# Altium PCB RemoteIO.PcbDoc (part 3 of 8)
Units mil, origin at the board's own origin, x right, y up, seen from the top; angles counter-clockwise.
Board outline 7874.02 x 2362.2 mil, 6 copper layers (Top Layer, GND1, Layer 2, PWR, GND2, Bottom Layer), stack 60.956 mil thick; 655 components, 447 nets, 2607 pads, 1444 vias.
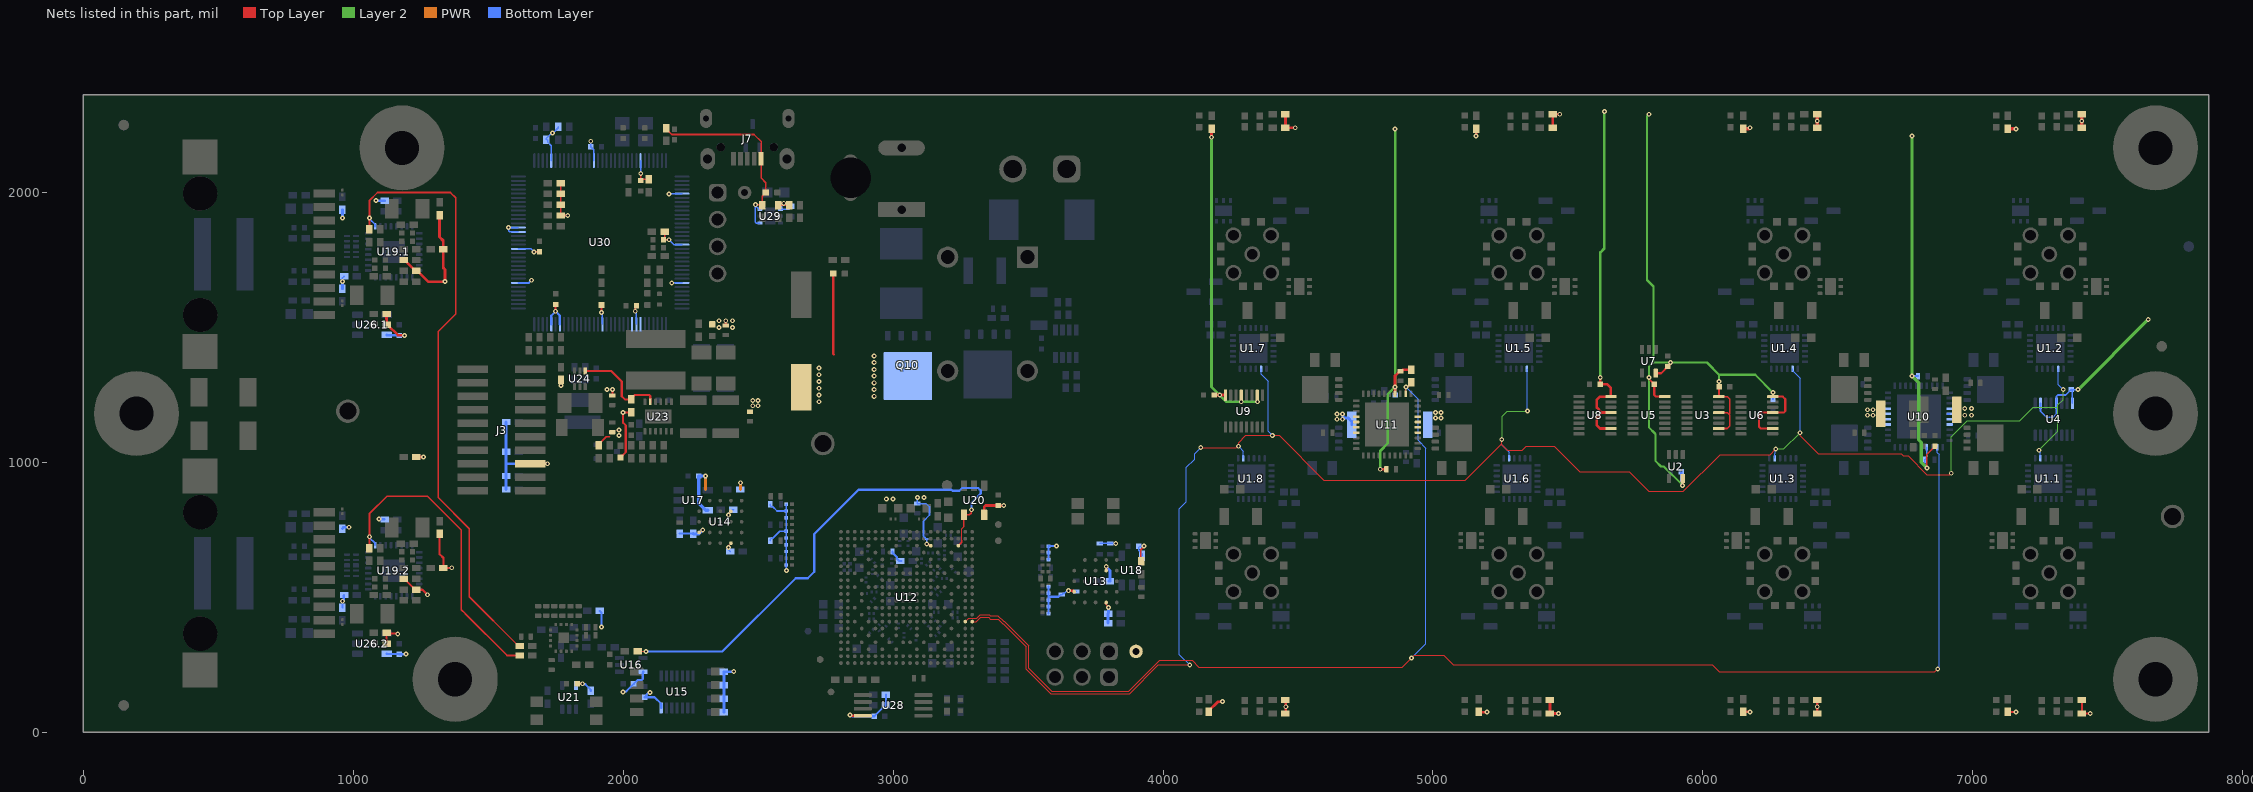
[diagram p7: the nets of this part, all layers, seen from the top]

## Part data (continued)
C11 C12 C13 C14 C16 C17 C18 C19: library part CMP-0119538-1, "WCAP-CSGP Multilayer Ceramic Chip Capacitor, General Purpose, size 0805, X7R, 22nF, 100VDC", Capacitance Tolerance=+/-10%, Case/Size Code=0805, Insulation Resistance=4.5GOhm, Manufacturer="Wurth Elektronik", Operating Temperature Max=125°C, Operating Temperature Min=-55°C, Rated Voltage (DC)=100V
C15 C20: library part CMP-0097308-1, "100 pF ±5% 100V Ceramic Capacitor C0G, NP0 0402 (1005 Metric)", Digikey Part Number=732-12055-1-ND, Manufacturer="Wurth Electronics", Mouser Part Number=710-885012005080, Operating Temperature Range="-55°C to +125°C", TempCo=30ppm/°C, Temperature Characteristic=NP0, Tolerance_%=5%, ValueDisplayed=100pF
C21 C22 C148 C163: library part CMP-0119705-1, "WCAP-CSGP Multilayer Ceramic Chip Capacitor, General Purpose, size 1210, X7R, 2.2µF, 100VDC", Capacitance Tolerance=+/-10%, Case/Size Code=1210, Insulation Resistance=0.05GOhm, Manufacturer="Wurth Elektronik", Operating Temperature Max=125°C, Operating Temperature Min=-55°C, PartNumber='885012209071, Rated Voltage (DC)=100V
C25 C26 C27 C28 C29 C32 C35 C39 C41 C42 C43 C130.1 C130.2 C133.1 C133.2 C136.1 C136.2 C138.1 C138.2 C144 C146 C154 C155 C158 C159 C164: library part CMP-0064924-2, "CAP, CERM, 1 uF, 10 V,+/- 20%, X5R, 0402", Cap_Case=0402, Manufacturer="Wurth Elektronik", Supplier Part Number 1=732-7489-1-ND, TempCo=X5R, Tolerance_%=20%, Value1=Unknown, Value2=10V, ValueDisplayed=1uF
C31 C131.1 C131.2 C134.1 C134.2 C145 C147 C156: library part CMP-0119242-1, "WCAP-CSGP Multilayer Ceramic Chip Capacitor, General Purpose, size 0402, X7R, 10nF, 10VDC", Capacitance Tolerance=+/-10%, Case/Size Code=0402, Insulation Resistance=10GOhm, Manufacturer="Wurth Elektronik", Operating Temperature Max=125°C, Operating Temperature Min=-55°C, Rated Voltage (DC)=10V
C44 C45 C46 C61 C63 C65 C66 C75 C84 C86 C91 C92 C93 C100 C121 C123 C125: library part CMP-0119149-1, "WCAP-CSGP Multilayer Ceramic Chip Capacitor, General Purpose, size 0603, X5R, 4.7µF, 6.3VDC", Capacitance Tolerance=+/-20%, Case/Size Code=0603, Insulation Resistance=0.02GOhm, Manufacturer="Wurth Elektronik", Operating Temperature Max=85°C, Operating Temperature Min=-55°C, Rated Voltage (DC)=6.3V
C47 C48 C49 C50 C51 C52 C53 C54 C55 C56 C57 C58 C59 C60 C62 C64 C67 C68 C69 C70 C71 C72 C73 C74 C76 C77 C78 C79 C80 C81 C82 C83 C85 C87 C88 C89 C90 C94 C95 C96 C97 C98 C99 C101 C102 C122 C124 C126: library part CMP-0119120-1, "WCAP-CSGP Multilayer Ceramic Chip Capacitor, General Purpose, size 0201, X5R Class II, 100nF, 6.3VDC", Capacitance Tolerance=+/-10%, Case/Size Code=0201, Insulation Resistance=0.5GOhm, Manufacturer="Wurth Elektronik", Operating Temperature Max=85°C, Operating Temperature Min=-55°C, Rated Voltage (DC)=6.3V
C104 C105 C106 C107 C120: library part CMP-0096739-1, "4.7 µF ±10% 50V Ceramic Capacitor X7R 1210 (3225 Metric)", Digikey Part Number=732-7386-1-ND, Manufacturer=Wurth, Mouser Part Number=710-885012209048, Operating Temperature Range="-55°C to +125°C", TempCo=15%, Temperature Characteristic=X7R, Tolerance_%=10%, ValueDisplayed=4.7uF
C108 C109 C115: library part CMP-0064937-2, "CAP, CERM, 22 uF, 10 V,+/- 10%, X7R, 1206", Cap_Case=1206, Manufacturer="Wurth Elektronik", Supplier Part Number 1=732-7566-1-ND, TempCo=X7R, Tolerance_%=10%, Value1=Unknown, Value2=10V, ValueDisplayed=22uF
C110 C111 C113 C129.1 C129.2 C132.1 C132.2: library part CMP-0750070-1, "CAP, CERM, 10 µF, 16 V,+/- 10%, X7R, 1206", Cap_Case=1206, Manufacturer="Wurth Elektronik", TempCo=X7R, Tolerance_%=10%, Value2=16V, ValueDisplayed=10µF
C112 C114: library part CMP-0112443-1, "WCAP-CSRF Multilayer Ceramic Chip Capacitor, High Frequency, size 0402, NP0 Class I, 27pF, 50VDC", Capacitance Tolerance=+/-5%, Case/Size Code=0402, Insulation Resistance=10GOhm, Manufacturer="Wurth Elektronik", Operating Temperature Max=125°C, Operating Temperature Min=-55°C, Rated Voltage (DC)=50V
C116: library part CMP-0114361-1, "WCAP-AS5H Aluminum Electrolytic Capacitor, V-Chip, D10 x H10.5mm, 220µF, 35V", Capacitance Tolerance=+/-20%, Leakage Current=77uA, Manufacturer="Wurth Elektronik", Operating Temperature Max=105°C, Operating Temperature Min=-40°C, Rated Voltage (DC)=35V, Ripple Current=280mA
C118: library part CMP-0119630-1, "WCAP-CSGP Multilayer Ceramic Chip Capacitor, General Purpose, size 1206, X7R, 100nF, 50VDC", Capacitance Tolerance=+/-10%, Case/Size Code=1206, Insulation Resistance=5GOhm, Manufacturer="Wurth Elektronik", Operating Temperature Max=125°C, Operating Temperature Min=-55°C, Rated Voltage (DC)=50V
C119: library part CMP-0077091-1, "CAP, CERM, 27 pF, 25 V,+/- 5%, C0G/NP0, 0402", Cap_Case=0402, Manufacturer=MuRata, Supplier Part Number 1=490-6176-1-ND, TempCo=C0G/NP0, Tolerance_%=5%, Value2=25V, ValueDisplayed=27pF
C127.1 C127.2: library part CMP-0006473-2, "CAP, CERM, 4.7 pF, 50 V, +/- 1%, C0G/NP0, 0402", Cap_Case=0402, Manufacturer=MuRata, Supplier Part Number 1=490-8210-1-ND, TempCo=C0G/NP0, Tolerance_%=1%, Value1=Unknown, Value2=50V, ValueDisplayed=4.7pF
C128.1 C128.2: library part CMP-0119293-1, "WCAP-CSGP Multilayer Ceramic Chip Capacitor, General Purpose, size 0402, X7R, 2.2nF, 50VDC", Capacitance Tolerance=+/-10%, Case/Size Code=0402, Insulation Resistance=10GOhm, Manufacturer="Wurth Elektronik", Operating Temperature Max=125°C, Operating Temperature Min=-55°C, Rated Voltage (DC)=50V
C140.1 C140.2: library part CMP-0009301-2, "CAP, CERM, 0.01 uF, 2000 V, +/- 10%, X7R, 1825", Cap_Case=1825, Manufacturer=AVX, Supplier Part Number 1=478-4008-1-ND, TempCo=X7R, Tolerance_%=10%, Value1=Unknown, Value2=2000V, ValueDisplayed=0.01uF
C160 C161: library part CMP-0124909-1, "12 pF ±2% 50V Ceramic Capacitor C0G, NP0 0402 (1005 Metric)", Digikey Part Number=732-885392005127CT-ND, Manufacturer=Wurth, Mouser Part Number=710-885392005127, Operating Temperature Range="-55°C to +125°C", TempCo=30ppm/°C, Temperature Characteristic=NP0, Tolerance_%=2%, ValueDisplayed=12pF
D1 D2 D3 D4 D5 D6 D7 D8: library part CMP-0125609-1, "Green, Red 520nm Green, 625nm Red LED Indication - Discrete 3.2V Green, 2V Red 0606 (1616 Metric)", Color="Red, Green", Digikey Part Number=732-150066RG74000CT-ND, Forward Current=20mA, Manufacturer=Wurth, Mouser Part Number=710-150066RG74000, Operating Temperature Range="-40°C to +85°C"
D9 D10 D11 D12 D13 D14 D15 D16 D20 D21 D22 D24 D29 D30 D31: library part CMP-0081765-2, "LED, Green, SMD", Color=Green, Manufacturer="Wurth Elektronik", Power_TotalModule=99mW, Value1=0.099W, Value2=3.2V
D23 D28: library part CMP-0122246-1, "Red 624nm LED Indication - Discrete 2V 0402 (1005 Metric)", Color=Red, Digikey Part Number=732-13422-1-ND, Forward Current=20mA, Manufacturer=Wurth, Mouser Part Number=710-150040RS73240, Operating Temperature Range="-40°C to +85°C", Power_TotalModule=48mW
D25: library part CMP-0005695-3, "Diode, TVS, Bi, 33 V, SMC", Manufacturer=Bourns, Value1=1500W
D26.1 D26.2 D27.1 D27.2: library part CMP-0120655-1, "1-pF, 5.5-V, 30-KV ESD protection device in 0201 package 2-X2SON -40 to 125", Breakdown Voltage=6V, Clamping Voltage=3.8V, Digikey Part Number=296-ESD441DPLRTR-ND, Manufacturer="Texas Instruments", Mouser Part Number=595-ESD441DPLR, Operating Temperature Range="-40°C to +125°C", ValueDisplayed=1pF
D35: library part CMP-0091708-1, "12.4V (Typ) Clamp 5.5A (8/20µs) Ipp Tvs Diode Surface Mount SC-70-3", Breakdown Voltage=6.5V, Clamping Voltage=9.7V, Digikey Part Number=296-TPD2E2U06DCKRCT-ND, Manufacturer="Texas Instruments", Mouser Part Number=595-TPD2E2U06DCKR, Operating Temperature Range="-40°C to +125°C", ValueDisplayed=1.5pF
F1: library part CMP-0003609-2, "Fuse, 10 A, 125 VAC, 72 VDC, SMD", Irating_A=10A, Manufacturer=Eaton, Supplier Part Number 1=283-2961-1-ND
FID1 FID2 FID3 FID4 FID5 FID6: library part CMP-0077181-1, "Fiducial mark.  There is nothing to buy or mount.", Manufacturer=N/A
H1 H2 H3 H9 H11 H12: library part CMP-0003617-1, "Machine Screw, Round, #4-40 x 1/4, Nylon, Philips panhead", Manufacturer="B&F Fastener Supply", Supplier Part Number 1=H542-ND
H5 H6 H7 H10 H13 H14: library part CMP-0003610-1, "Standoff, Hex, 0.5\"L #4-40 Nylon", Manufacturer=Keystone, Supplier Part Number 1=36-1902C-ND
J1.1 J1.2 J1.3 J1.4 J1.5 J1.6 J1.7 J1.8: "WR-CIRCM12 Screw Mating Panel Connector Female Metal PG9, THT, 5p", Insulation Resistance=100MΩ, Manufacturer="Wurth Elektronik", Max Operating Temperature=90°C, Min Operating Temperature=-40°C, PartNumber='643260100605, Rated Current=5A, Withstanding Voltage="1000V AC", Working Voltage=60V
J2: library part CMP-0127094-1, "Power Barrel Connector Jack 2.10mm ID (0.083\"), 5.50mm OD (0.217\") Through Hole, Right Angle", Current_A=5A, Digikey Part Number=732-5930-ND, Manufacturer=Wurth, Mouser Part Number=710-694106301002, Operating Temperature Range="-40°C to +85°C", Voltage_V=30V
J3: library part CMP-0075640-2, "Header, 1.27mm, 10x2, Tin, SMT", Color=Black, Current_A=3.1A, Manufacturer=Samtec, Supplier Part Number 1=SAM8792-ND
J4.1 J4.2: "WE-RJ45 LAN Transformer, SMT, 10/100 Base-T, Tab Down, 1 Port", Manufacturer="Wurth Elektronik", Max Operating Temperature=85°C, Min Operating Temperature=-40°C
J5: "WR-TBL Series 3055 PCB Header Horizontal Entry with Plastic Latches, THT, pitch 5.08mm, 02p", Manufacturer="Wurth Elektronik", Max Operating Temperature=105°C, Min Operating Temperature=-40°C, Rated Current=16A, Working Voltage=300V
J6: library part CMP-0054798-2, "Header, 2.54 mm, 4x1, Gold, TH", Color=Black, Manufacturer="Wurth Elektronik", PartNumber=61300411121, Supplier Part Number 1=732-5317-ND
J7: library part CMP-0086695-3, "USB - micro B USB 2.0 Receptacle Connector 5 Position Surface Mount, Right Angle; Through Hole", Current_A=3A, Manufacturer="Wurth Electronics", Voltage_V=30V
J8 J9: library part CMP-0054796-4, "Header, 2.54 mm, 3x1, Gold, TH", Manufacturer="Wurth Elektronik", Supplier Part Number 1=732-5316-ND
L1 L7.1 L7.2 L8.1 L8.2 L9: library part CMP-0003233-1, "Ferrite Bead, 600 ohm @ 100 MHz, 0.3 A, 0402", Manufacturer="Wurth Elektronik", Supplier Part Number 1=732-2388-1-ND, Value1="0.6 ohm", Value2=0.3A, ValueDisplayed="600 ohm"
L2 L3: library part CMP-0003214-1, "Ferrite Bead, 120 ohm @ 100 MHz, 0.5 A, 0402", Manufacturer="Wurth Elektronik", Supplier Part Number 1=710-74279271, Value1="0.2 ohm", Value2=0.5A, ValueDisplayed="120 ohm"
L4: library part CMP-0099177-1, "WE-MAPI SMT Power Inductor, size 5030, 6.8uH, 4.3A, 48.3mOhm", Case/Size Code=5030, DC Resistance=42mOhm, DC Resistance Max=48.3mOhm, Inductance=6.8uH, Manufacturer="Wurth Elektronik", Operating Temperature Max=125°C, Operating Temperature Min=-40°C, Rated Current=4.3A, Saturation Current=5.7A, Self Resonant Frequency=15.5MHz
L5: library part CMP-0099114-2, "WE-MAPI SMT Power Inductor, size 3020, 1uH, 4A, 32mOhm", Case/Size Code=3020, DC Resistance=26mOhm, DC Resistance Max=32mOhm, Inductance=1uH, Manufacturer="Wurth Elektronik", Operating Temperature Max=125°C, Operating Temperature Min=-40°C, Rated Current=4A, Saturation Current=5A, Self Resonant Frequency=67MHz
L6: library part CMP-0098028-1, "2 mH @ 10 kHz 2 Line Common Mode Choke Through Hole 10A DCR 6mOhm", Digikey Part Number=732-5584-ND, Manufacturer="Wurth Electronics", Mouser Part Number=710-7448031002, Operating Temperature Range="-40°C to +125°C", Test Frequency=10kHz, Tolerance_%=50%
LBL1: library part CMP-0003625-1, "Thermal Transfer Printable Labels, 0.650\" W x 0.200\" H - 10,000 per roll", Manufacturer=Brady, Supplier Part Number 1=97C5133
Logo1: library part CMP-0074838-1, "Texas Instrument Corporate Signature"
Logo2: library part CMP-0074844-1
Logo3: library part CMP-0074847-1, "FCC_disclaimer"
Logo4: library part CMP-0074769-1
Q1 Q2 Q3 Q4 Q5 Q6 Q7 Q8: library part CMP-0000826-2, "MOSFET, N-CH, 60 V, 35 A, DNH0008A (VSONP-8)", Alternate Manufacturer=None, Manufacturer="Texas Instruments", Supplier Part Number 1=CSD18543Q3A-ND, Value1=0.01, Value2="11.1 nC"
Q9 Q10: library part CMP-0000810-1, "MOSFET, N-CH, 60 V, 100 A, DQJ0008A (VSONP-8)", Alternate Manufacturer=None, Manufacturer="Texas Instruments", Supplier Part Number 1=296-30573-1-ND, Value1=0.005, Value2="36 nC"
Q11: library part CMP-0000486-2, "Transistor, NPN, 45 V, 0.1 A, AEC-Q101, SOT-323", Manufacturer="NXP Semiconductor", Supplier Part Number 1=568-6067-1-ND, Value1="0.1 A", Value2=800
R1.1 R1.2 R1.3 R1.4 R1.5 R1.6 R1.7 R1.8 R27 R28 R30 R33 R34 R35 R37 R73 R85 R87 R88 R98 R99 R101 R102 R103 R104 R105 R106 R107 R108 R109 R110 R111 R112 R117 R125 R137 R139 R155 R156 R157 R158 R159 R160 R161 R162: library part CMP-0093210-1, "Jumper 0.063W, 1/16W Chip Resistor 0402 (1005 Metric) - Thick Film", Digikey Part Number=541-4062-1-ND, Manufacturer=Vishay, Mouser Part Number=71-CRCW04020000Z0EDC, Operating Temperature Range="-55°C to +155°C", Power_W=63mW
R2.1 R2.2 R2.3 R2.4 R2.5 R2.6 R2.7 R2.8 R29 R42 R43 R63 R64 R89 R90 R91 R92 R94 R95 R96 R97 R100 R113 R141 R144 R145 R146 R147 R148 R149 R150 R164.1 R164.2 R189.1 R189.2 R190.1 R190.2 R208 R209: library part CMP-0026825-5, "RES, 10 k, 5%, 0.063 W, AEC-Q200 Grade 0, 0402", Manufacturer=Vishay-Dale, Power_W=63mW, Supplier Part Number 1=541-10KJCT-ND, TempCo="200 ppm/C", Tolerance_%=5%, Value2=0.063W, Value_Code=10k0, ValueDisplayed=10k
R3 R4 R5 R6 R7 R8 R9 R10 R11 R12 R13 R14 R15 R16 R17 R18 R32 R36 R61 R83 R123 R143 R197 R198 R199 R200 R206: library part CMP-0026071-3, "RES, 1.00 k, 1%, 0.063 W, AEC-Q200 Grade 0, 0402", Manufacturer=Vishay-Dale, Power_W=63mW, Supplier Part Number 1=541-1.00KLCT-ND, TempCo="100 ppm/C", Tolerance_%=1%, Value2=0.063W, Value_Code=1k00, ValueDisplayed=1.00k
R19 R20 R21 R22 R23 R24 R25 R26 R138 R140 R142 R195 R207: library part CMP-0026918-5, "RES, 3.3 k, 5%, 0.063 W, AEC-Q200 Grade 0, 0402", Manufacturer=Vishay-Dale, Power_W=63mW, Supplier Part Number 1=541-3.3KJCT-ND, TempCo="200 ppm/C", Tolerance_%=5%, Value2=0.063W, Value_Code=3k30, ValueDisplayed=3.3k
R31: library part CMP-0026004-3, "RES, 13.3 k, 1%, 0.063 W, AEC-Q200 Grade 0, 0402", Manufacturer=Vishay-Dale, Power_W=63mW, Supplier Part Number 1=541-13.3KLCT-ND, TempCo="100 ppm/C", Tolerance_%=1%, Value2=0.063W, Value_Code=13k3, ValueDisplayed=13.3k
R38: library part CMP-0026187-2, "RES, 23.7 k, 1%, 0.063 W, AEC-Q200 Grade 0, 0402", Manufacturer=Vishay-Dale, Power_W=63mW, Supplier Part Number 1=541-23.7KLCT-ND, TempCo="100 ppm/C", Tolerance_%=1%, Value2=0.063W, Value_Code=23k7, ValueDisplayed=23.7k
R39 R40 R118 R119 R120: library part CMP-0026908-3, "RES, 33, 5%, 0.063 W, AEC-Q200 Grade 0, 0402", Manufacturer=Vishay-Dale, Power_W=63mW, Supplier Part Number 1=541-33JCT-ND, TempCo="200 ppm/C", Tolerance_%=5%, Value2=0.063W, Value_Code=33R0, ValueDisplayed=33
R41: library part CMP-0026890-5, "RES, 2.2 k, 5%, 0.063 W, AEC-Q200 Grade 0, 0402", Manufacturer=Vishay-Dale, Power_W=63mW, Supplier Part Number 1=541-2.2KJCT-ND, TempCo="200 ppm/C", Tolerance_%=5%, Value2=0.063W, Value_Code=2k20, ValueDisplayed=2.2k
R44 R45 R47 R48 R49 R50 R51 R65 R66 R68 R69 R70 R71 R72: library part CMP-0028027-1, "RES, 49.9 k, 1%, 0.05 W, 0201", Manufacturer="Yageo America", Power_W=50mW, Supplier Part Number 1=603-RC0201FR-7D49K9L, TempCo="200 ppm/C", Tolerance_%=1%, Value2=0.05W, Value_Code=49k9, ValueDisplayed=49.9k
R46 R67: library part CMP-0027242-1, "RES, 4.7 k, 5%, 0.05 W, 0201", Manufacturer="Yageo America", Power_W=50mW, Supplier Part Number 1=603-RC0201JR-7D4K7L, TempCo="200 ppm/C", Tolerance_%=5%, Value2=0.05W, Value_Code=4k70, ValueDisplayed=4.7k
R52 R53 R54 R55 R56 R57 R58 R59 R60 R74 R75 R76 R77 R78 R79 R80 R81 R82: library part CMP-0027210-3, "RES, 22, 5%, 0.05 W, 0201", Manufacturer="Yageo America", Power_W=50mW, Supplier Part Number 1=603-RC0201JR-7D22RL, TempCo="200 ppm/C", Tolerance_%=5%, Value2=0.05W, Value_Code=22R0, ValueDisplayed=22
R62 R84 R121 R122 R127 R128 R129 R130 R131 R134: library part CMP-0026721-1, "RES, 100 k, 1%, 0.0625 W, 0402", Manufacturer="Yageo America", Power_W=62.5mW, Supplier Part Number 1=311-100KLRCT-ND, TempCo="100 ppm/C", Tolerance_%=1%, Value2=0.0625W, Value_Code=100k
R86 R114 R115: library part CMP-0027008-4, "RES, 0, 5%, 0.05 W, 0201", Manufacturer=Vishay-Dale, Power_W=50mW, Supplier Part Number 1=72M6743, TempCo=ppm/C, Tolerance_%=5%, Value2=0.05W, Value_Code=0000, ValueDisplayed=0
R93: library part CMP-0026964-3, "RES, 68, 5%, 0.063 W, AEC-Q200 Grade 0, 0402", Manufacturer=Vishay-Dale, Power_W=63mW, Supplier Part Number 1=541-68JCT-ND, TempCo="200 ppm/C", Tolerance_%=5%, Value2=0.063W, Value_Code=68R0, ValueDisplayed=68
R124: library part CMP-0026290-2, "RES, 31.6 k, 1%, 0.063 W, AEC-Q200 Grade 0, 0402", Manufacturer=Vishay-Dale, Power_W=63mW, Supplier Part Number 1=541-31.6KLCT-ND, TempCo="100 ppm/C", Tolerance_%=1%, Value2=0.063W, Value_Code=31k6, ValueDisplayed=31.6k
R126: library part CMP-0025956-3, "RES, 107 k, 1%, 0.063 W, AEC-Q200 Grade 0, 0402", Manufacturer=Vishay-Dale, Power_W=63mW, Supplier Part Number 1=541-107KLCT-ND, TempCo="100 ppm/C", Tolerance_%=1%, Value2=0.063W, Value_Code=107k
R132: library part CMP-0026340-2, "RES, 3.92 k, 1%, 0.063 W, AEC-Q200 Grade 0, 0402", Manufacturer=Vishay-Dale, Power_W=63mW, Supplier Part Number 1=541-3.92KLCT-ND, TempCo="100 ppm/C", Tolerance_%=1%, Value2=0.063W, Value_Code=3k92, ValueDisplayed=3.92k
R133: library part CMP-0026555-2, "RES, 7.50 k, 1%, 0.063 W, AEC-Q200 Grade 0, 0402", Manufacturer=Vishay-Dale, Power_W=63mW, Supplier Part Number 1=541-7.50KLCT-ND, TempCo="100 ppm/C", Tolerance_%=1%, Value2=0.063W, Value_Code=7k50, ValueDisplayed=7.50k
R135: library part CMP-0026592-2, "RES, 8.87 k, 1%, 0.063 W, AEC-Q200 Grade 0, 0402", Manufacturer=Vishay-Dale, Power_W=63mW, Supplier Part Number 1=541-8.87KLCT-ND, TempCo="100 ppm/C", Tolerance_%=1%, Value2=0.063W, Value_Code=8k87, ValueDisplayed=8.87k
R136: library part CMP-0026963-3, "RES, 68 k, 5%, 0.063 W, AEC-Q200 Grade 0, 0402", Manufacturer=Vishay-Dale, Power_W=63mW, Supplier Part Number 1=541-68KJCT-ND, TempCo="200 ppm/C", Tolerance_%=5%, Value2=0.063W, Value_Code=68k0, ValueDisplayed=68k
R151 R152 R153 R154 R203 R204 R205 R212: library part CMP-0026880-3, "RES, 22, 5%, 0.063 W, AEC-Q200 Grade 0, 0402", Manufacturer=Vishay-Dale, Power_W=63mW, Supplier Part Number 1=541-22JCT-ND, TempCo="200 ppm/C", Tolerance_%=5%, Value2=0.063W, Value_Code=22R0, ValueDisplayed=22
R163.1 R163.2: library part CMP-0026515-2, "RES, 6.49 k, 1%, 0.063 W, AEC-Q200 Grade 0, 0402", Manufacturer=Vishay-Dale, Power_W=63mW, Supplier Part Number 1=541-6.49KLCT-ND, TempCo="100 ppm/C", Tolerance_%=1%, Value2=0.063W, Value_Code=6k49, ValueDisplayed=6.49k
R166.1 R166.2 R167.1 R167.2 R168.1 R168.2 R171.1 R171.2 R172.1 R172.2: library part CMP-0026237-2, "RES, 2.49 k, 1%, 0.063 W, AEC-Q200 Grade 0, 0402", Manufacturer=Vishay-Dale, Power_W=63mW, Supplier Part Number 1=541-2.49KLCT-ND, TempCo="100 ppm/C", Tolerance_%=1%, Value2=0.063W, Value_Code=2k49, ValueDisplayed=2.49k
R176.1 R176.2 R177.1 R177.2 R178.1 R178.2 R181.1 R181.2 R182.1 R182.2: library part CMP-0026088-3, "RES, 1.50 k, 1%, 0.063 W, AEC-Q200 Grade 0, 0402", Manufacturer=Vishay-Dale, Power_W=63mW, Supplier Part Number 1=541-1.50KLCT-ND, TempCo="100 ppm/C", Tolerance_%=1%, Value2=0.063W, Value_Code=1k50, ValueDisplayed=1.50k
R191.1 R191.2 R192.1 R192.2: library part CMP-0025756-4, "RES, 220, 5%, 0.1 W, AEC-Q200 Grade 0, 0603", Manufacturer=Vishay-Dale, Power_W=100mW, Supplier Part Number 1=541-220GCT-ND, TempCo="200 ppm/C", Tolerance_%=5%, Value2=0.1W, Value_Code=220R, ValueDisplayed=220
R193.1 R193.2: library part CMP-0016081-3, "RES, 1.0 M, 5%, 0.75 W, AEC-Q200 Grade 0, 2010", Manufacturer=Vishay-Dale, Power_W=750mW, Supplier Part Number 1=541-1.0MWCT-ND, TempCo="200 ppm/C", Tolerance_%=5%, Value2=0.75W, Value_Code=1M00, ValueDisplayed=1.0M
R194: library part CMP-0026441-2, "RES, 52.3 k, 1%, 0.063 W, AEC-Q200 Grade 0, 0402", Manufacturer=Vishay-Dale, Power_W=63mW, Supplier Part Number 1=541-52.3KLCT-ND, TempCo="100 ppm/C", Tolerance_%=1%, Value2=0.063W, Value_Code=52k3, ValueDisplayed=52.3k
R196: library part CMP-0078244-2, "RES, 30.0 k, 1%, 0.063 W, AEC-Q200 Grade 0, 0402", Manufacturer=Vishay-Dale, Power_W=63mW, Supplier Part Number 1=541-30.0KLCT-ND, TempCo="100 ppm/C", Tolerance_%=1%, Value2=0.063W, Value_Code=30k0, ValueDisplayed=30.0k
R201: library part CMP-0026824-3, "RES, 100, 5%, 0.063 W, AEC-Q200 Grade 0, 0402", Manufacturer=Vishay-Dale, Power_W=63mW, Supplier Part Number 1=541-100JCT-ND, TempCo="200 ppm/C", Tolerance_%=5%, Value2=0.063W, Value_Code=100R, ValueDisplayed=100
R210: library part CMP-0026413-2, "RES, 4.87 k, 1%, 0.063 W, AEC-Q200 Grade 0, 0402", Manufacturer=Vishay-Dale, Power_W=63mW, Supplier Part Number 1=541-4.87KLCT-ND, TempCo="100 ppm/C", Tolerance_%=1%, Value2=0.063W, Value_Code=4k87, ValueDisplayed=4.87k
R211: library part CMP-0026946-3, "RES, 51, 5%, 0.063 W, AEC-Q200 Grade 0, 0402", Manufacturer=Vishay-Dale, Power_W=63mW, Supplier Part Number 1=541-51JCT-ND, TempCo="200 ppm/C", Tolerance_%=5%, Value2=0.063W, Value_Code=51R0, ValueDisplayed=51
R213: library part CMP-0025862-4, "RES, 8.2 k, 5%, 0.1 W, AEC-Q200 Grade 0, 0603", Manufacturer=Vishay-Dale, Power_W=100mW, Supplier Part Number 1=541-8.2KGCT-ND, TempCo="200 ppm/C", Tolerance_%=5%, Value2=0.1W, Value_Code=8k20, ValueDisplayed=8.2k
RV1.1 RV1.2 RV1.3 RV1.4 RV1.5 RV1.6 RV1.7 RV1.8 RV2.1 RV2.2 RV2.3 RV2.4 RV2.5 RV2.6 RV2.7 RV2.8 RV3.1 RV3.2 RV3.3 RV3.4 RV3.5 RV3.6 RV3.7 RV3.8 RV4.1 RV4.2 RV4.3 RV4.4 RV4.5 RV4.6 RV4.7 RV4.8 RV5.1 RV5.2 RV5.3 RV5.4 RV5.5 RV5.6 RV5.7 RV5.8 RV6.1 RV6.2 RV6.3 RV6.4 RV6.5 RV6.6 RV6.7 RV6.8: library part 82556300, "WE-VS SMT Varistor, size 0603, 30VAC, 38VDC", (Reverse) Breakdown Voltage=47V, (Reverse) Peak Pulse Current=30A, Case/Size Code=0603, Clamping Voltage=77V, Manufacturer="Wurth Elektronik", Max Operating Temperature=85°C, Min Operating Temperature=-40°C, Operating Voltage (AC)=30V, Operating Voltage (DC)=38V
S1: library part CMP-0002302-1, "Switch, SPST, Off-Mom, 0.05 A, 12 VDC, SMD", CurrentRating_mA=50A, Manufacturer="Wurth Elektronik", Supplier Part Number 1=732-10143-1-ND
SW1: library part CMP-0093176-1, "Dip Switch SPST 4 Position Surface Mount Slide (Standard) Actuator 25mA 24VDC", Coil Resistance_ohm=100mΩ, Contact Current Rating=25mA, Digikey Part Number=732-3854-1-ND, Manufacturer=Wurth, Mouser Part Number=710-416131160804, Operating Temperature Range="-40°C to +85°C"
SW2: library part CMP-0093456-1, "Tactile Switch SPST-NO Side Actuated Surface Mount, Right Angle", Coil Resistance_ohm=100mΩ, Contact Current Rating=50mA, Digikey Part Number=732-7057-1-ND, Manufacturer="Wurth Electronics", Mouser Part Number=710-434351045816, Operating Force=160gf, Operating Temperature Range="-40°C to +85°C"
TP1 TP2: library part CMP-0003825-1, "1mm Test Point, SMT", Manufacturer=Any
TP3 TP4 TP5: library part CMP-0055143-2, "Test Point, Compact, Black, TH", Color=Black, Manufacturer="Keystone Electronics", Supplier Part Number 1=36-5006-ND
TP6 TP7 TP8 TP9 TP10 TP11 TP12: library part CMP-0078143-4, "TEST POINT.  No entry in BOM.", Manufacturer=N/A
U1.1 U1.2 U1.3 U1.4 U1.5 U1.6 U1.7 U1.8: library part CMP-0044977-1, "Dual Channel IO-Link Device PHY with Integrated LDO and SPI Interface", Manufacturer="Texas Instruments", Max Supply Voltage=36V, Min Supply Voltage=4.5V, Operating Temperature Range="-40°C to +150°C"
U2: library part CMP-0051326-3, "Single Bus Buffer Gate With 3-State Outputs, DCK0005A, LARGE T&R", F @ Nom Voltage(Max)(Mhz)=150, Generic Part Number=SN74LVC1G125, ICC @ Nom Voltage(Max)(mA)=0.01, Manufacturer="Texas Instruments", Operating Temperature Range(C)="-40 to 125,-40 to 85", Rating=Catalog, tpd @ Nom Voltage(Max)(ns)=9,5.5,4.5,4, Voltage(Nom)(V)=1.8,2.5,3.3,5
U3 U4 U6 U8 U9: library part CMP-0093041-1, "Eight-bit shift registers with Schmitt-trigger inputs and with output registers", Digikey Part Number=296-SN74HCS594DYYRCT-ND, Frequency_Fixed=115MHz, Manufacturer="Texas Instruments", Max Supply Voltage=6V, Min Supply Voltage=2V, Mouser Part Number=595-SN74HCS594DYYR, Nominal Supply Current=0.1uA, Operating Temperature Range="-40°C to +125°C"
U5: library part CMP-0093040-1, "Counter Shift Registers 8-bit parallel-load shift registers with Schmitt-trigger inputs", Frequency_Fixed=170MHz, Manufacturer="Texas Instruments", Max Supply Voltage=6V, Min Supply Voltage=2V, Mouser Part Number=595-SN74HCS165DYYR, Nominal Supply Current=0.1uA, Operating Temperature Range="-40°C to +125°C"
U7: library part CMP-0051641-4, "Single Schmitt-Trigger Inverter, DCK0005A (SOT-SC70-5)", Alternate Manufacturer="Texas Instruments", Alternate PartNumber=SN74LVC1G14DCKT, F @ Nom Voltage(Max)(Mhz)=150, Generic Part Number=SN74LVC1G14, ICC @ Nom Voltage(Max)(mA)=0.01, Operating Temperature Range="-40 to 125 C", Rating=Catalog, tpd @ Nom Voltage(Max)(ns)=11,6.5,5.5,5, Voltage(Nom)(V)=1.8,2.5,3.3,5
U10 U11: library part CMP-0093389-2, "65-mΩ, Quad-Channel Smart High-Side Switch with SPI interface and Diagnostics", Manufacturer="Texas Instruments", Max Supply Voltage=36V, Min Supply Voltage=3V, Operating Temperature Range="to +150°C"
U12: library part CMP-0126016-1, "ARM® Cortex®-R5F Sitara™ Microcontroller IC 32-Bit Dual-Core 500MHz 512KB (512K x 8) Tightly Coupled Memory (TCM) 304-NFBGA (13.25x13.25)", Digikey Part Number=296-AM2612AOFFHIZFGRCT-ND, Frequency_Fixed=500MHz, Manufacturer="Texas Instruments", Max Supply Voltage=3.465V, Min Supply Voltage=1.14V, Mouser Part Number=595-AM2612AOFFHIZFGR, Operating Temperature Range="-40°C to +125°C"
U13: library part CMP-0086110-1, "3V 512M-BIT [x 1/x 8] CMOS MXSMIO(R)(SERIAL MULTI I/O)FLASH MEMORY, BGA-24", Manufacturer="Macronix International Co., LTD"
U14: library part CMP-0126808-1, "DRAM IoT RAM 128Mb OPI (x8) DDR 133MHz, 3V, Ind. Temp., BGA24", Frequency_Fixed=133MHz, Manufacturer="AP Memory", Max Supply Voltage=3.6V, Min Supply Voltage=2.7V, Mouser Part Number=878-APS12808L3OBMBA, Nominal Supply Current=500-700uA, Operating Temperature Range="-40°C to +85°C"
U15: library part CMP-0127143-1, "Schmitt-trigger inputs quadruple bus buffer gates with 3-state outputs 14-SOT-23-THIN -40 to 125", Digikey Part Number=296-SN74HCS125DYYRCT-ND, Manufacturer="Texas Instruments", Max Supply Voltage=6V, Min Supply Voltage=2V, Mouser Part Number=595-SN74HCS125DYYR, Nominal Supply Current=0.1uA, Operating Temperature Range="-40°C to +125°C"
U16 U21: library part CMP-0051704-3, "Single Schmitt-Trigger Buffer, DCK0005A, LARGE T&R", F @ Nom Voltage(Max)(Mhz)=150, Generic Part Number=SN74LVC1G17, ICC @ Nom Voltage(Max)(mA)=0.01, Manufacturer="Texas Instruments", Operating Temperature Range(C)="-40 to 125,-40 to 85", Rating=Catalog, tpd @ Nom Voltage(Max)(ns)=11,6.5,5.5,5, Voltage(Nom)(V)=1.8,2.5,3.3,5
U17 U18 U26.1 U26.2: library part CMP-0051264-2, "Single 2-Input Positive–AND Gate with Open Drain Output,  DBV0005A (SOT-23-5)", F @ Nom Voltage(Max)(Mhz)=75, Generic Part Number=SN74AHC1G09, ICC @ Nom Voltage(Max)(mA)=0.01, Manufacturer="Texas Instruments", Operating Temperature Range="-55 to 125 C", Rating=Catalog, tpd @ Nom Voltage(Max)(ns)=11,7.5, Voltage(Nom)(V)=3.3,5
U19.1 U19.2: library part CMP-0124715-2, "Deterministic, Low-Latency, Low-Power, 10/100 Mbps, Industrial Ethernet PHY", Manufacturer="Texas Instruments", Max Supply Voltage=3.6V, Min Supply Voltage=1.62V, Operating Temperature Range="-40°C to +85°C"
U20: library part CMP-0051588-2, "Single 2-Input Positive-AND Gate, DBV0005A, LARGE T&R", Alternate Manufacturer="Texas Instruments", F @ Nom Voltage(Max)(Mhz)=150, Generic Part Number=SN74LVC1G08, ICC @ Nom Voltage(Max)(mA)=0.01, Operating Temperature Range(C)="-40 to 125,-40 to 85", Rating=Catalog, tpd @ Nom Voltage(Max)(ns)=4.5,6,4,5, Voltage(Nom)(V)=1.8,2.5,3.3,5
U22: library part CMP-0126121-1, "5 output reference-less clock generator with bulk acoustic wave (BAW) 16-TQFN -40 to 85", Digikey Part Number=296-LMK3C0105V33RERRTR-ND, Manufacturer="Texas Instruments", Max Frequency=200MHz, Max Supply Voltage=3.465V, Min Supply Voltage=1.71V, Mouser Part Number=595-LMK3C0105V33RERR, Operating Temperature Range="-40°C to +85°C"
U23: library part CMP-0096682-1, "4-V to 36-V, 5-A Synchronous Step-Down DC/DC Converter with Low IQ", Manufacturer="Texas Instruments", Max Supply Voltage=36V, Min Supply Voltage=4V, Nominal Supply Current=25uA, Operating Temperature Range="-40°C to +150°C", Output Voltage=1-16V, Switching Frequency=200-1100kHz
U24: library part CMP-0121127-1, "3-A, High-Efficiency, Synchronous Buck Converter in a SOT563 Package", Manufacturer="Texas Instruments", Max Supply Voltage=5.5V, Min Supply Voltage=2.5V, Nominal Supply Current=28.5uA, Operating Temperature Range="-40°C to +125°C", Output Voltage=0.6-5.5V, Switching Frequency=2.2MHz
U25: library part CMP-0095525-1, "Low IQ High Side Switch Controller With Reverse Polarity and Overvoltage Protection", Manufacturer="Texas Instruments", Max Supply Voltage=60V, Min Supply Voltage=4V, Nominal Supply Current=45uA, Operating Temperature Range="-40°C to +150°C"
U27.1 U27.2: library part CMP-0079927-2, "ESD204, DQA0010A (USON-10)", Alternate Manufacturer="Texas Instruments", Alternate PartNumber=ESD204DQAT
U28: library part CMP-0005248-2, "256K I2C™ CMOS Serial EEPROM, TSSOP-8", Manufacturer=Microchip, Supplier Part Number 1=24AA256-I/ST-ND
U29: library part CMP-0066914-5, "1% High-Accuracy, 1-A, Low-Dropout Regulator with Reverse Current Protection, DRV0006A (WSON-6)", Alternate Manufacturer="Texas Instruments", Alternate PartNumber=TPS7A3701DRVT
U30: library part CMP-0077953-1, "MSP432E401YTPDT, PDT0128A (TQFP-128)", Alternate Manufacturer="Texas Instruments", Alternate PartNumber=MSP432E401YTPDTR
U31.1 U31.2 U31.3 U31.4 U31.5 U31.6 U31.7 U31.8 U32.1 U32.2 U32.3 U32.4 U32.5 U32.6 U32.7 U32.8: library part CMP-0013424-7, "33-V Precision Surge Protection Clamp, DRV0006A (WSON-6)", Alternate Manufacturer="Texas Instruments", Alternate PartNumber=TVS3300DRVT
U33.1 U33.2 U33.3 U33.4 U33.5 U33.6 U33.7 U33.8 U34.1 U34.2 U34.3 U34.4 U34.5 U34.6 U34.7 U34.8: library part CMP-0097428-1, "Surge Protection Device in SOT-23 Package", Breakdown Voltage=37.8V, Clamping Voltage=57V, Manufacturer="Texas Instruments", Operating Supply Voltage=36V, Operating Temperature Range="-40°C to +125°C", ValueDisplayed=50pF
Y1: library part CMP-0094478-1, "Crystal 16 MHz ±20ppm Crystal 8pF 70 Ohms 4-SMD, No Lead", Digikey Part Number=732-830064296CT-ND, Frequency Stability=20ppm, Frequency_Fixed=16MHz, Load Capacitance=8pF, Manufacturer=Wurth, Mouser Part Number=710-830064296, Operating Temperature Range="-10°C to +70°C"
ZZ1: library part CMP-0003616-3
ZZ2: library part CMP-0077236-1
ZZ3: library part CMP-0077237-1
ZZ4: library part CMP-0077238-1

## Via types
v1: diameter 18, hole 8, Top Layer to Bottom Layer, tented both sides, 1277 vias
v2: diameter 19.68, hole 7.87, Top Layer to Bottom Layer, tented both sides, 133 vias
v3: diameter 19.68, hole 7.87, Top Layer to Bottom Layer, 34 vias

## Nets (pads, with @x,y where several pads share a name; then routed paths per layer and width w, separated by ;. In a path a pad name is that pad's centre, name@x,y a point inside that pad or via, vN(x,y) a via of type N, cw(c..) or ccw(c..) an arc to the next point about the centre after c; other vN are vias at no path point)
1V25: C80.2 R109.2 R125.2 R141.2 U12.V7 | length 313.4
  Top Layer w6: R141.2@1910,1063.62 1910,1067.56 1937.44,1095 1950,1095 ; R125.2@1960,1112.28 R125.2@1964.87,1117.16 ; v1@1978.91,1117.16 1981.75,1120 v1(1985,1120) ; v1(3124.83,698.51) 3127.12,696.21 3133.18,696.21 3137.46,691.93 U12.V7@3139.57,691.93
  Bottom Layer w6: v1(3090,870) R109.2@3090,847.72 3122.28,847.72 3135.04,834.96 3135.04,805.04 3112.59,782.59 3112.59,726.84 3116.84,722.59 3116.97,722.59 3123.23,716.34 C80.2@3125,716.34 ; v1(3124.83,698.51) 3124.91,698.59 3124.91,716.25 C80.2@3125,716.34 ; C80.2@3126.77,716.34 C80.2@3125,716.34
  other v1: 3115,870 1985,1100
3V3: C3.2 C4.2 C5.2 C6.2 C7.2 C8.2 C9.2 C10.2 C23.2 C24.2 C25.1 C26.1 C27.1 C28.1 C29.1 C30.2 C32.1 C33.2 C34.2 C36.2 C37.2 C38.2 C142.1.2 C142.2.2 C143.2 D21.2 D22.2 J3.5 L1.2 L3.2 L7.1.2 L7.2.2 L8.1.2 L8.2.2 R3.2 R4.2 R5.2 R6.2 R7.2 R8.2 R9.2 R10.2 R11.2 R12.2 R13.2 R14.2 R15.2 R16.2 R17.2 R18.2 R19.2 R20.2 R21.2 R22.2 R23.2 R24.2 R25.2 R26.2 R27.1 R28.2 R29.2 R33.1 R34.2 R41.1 R42.2 R43.2 R44.2 R45.2 R46.2 R47.2 R48.2 R49.2 R50.2 R51.2 R63.2 R64.2 R65.2 R66.2 R67.2 R68.2 R69.2 R70.2 R71.2 R72.2 R89.2 R90.2 R91.2 R92.2 R94.2 R95.2 R96.2 R97.2 R100.2 R110.2 R113.1 R117.2 R121.2 R127.2 R139.2 R145.1 R146.1 R147.2 R148.2 R149.2 R150.2 R164.1.2 R164.2.2 R166.1.2 R166.2.2 R167.1.2 R167.2.2 R168.1.2 R168.2.2 R171.1.2 R171.2.2 R172.1.2 R172.2.2 R189.1.2 R189.2.2 R190.1.2 R190.2.2 TP12.1 U2.5 U3.10 U3.13 U3.16 U4.10 U4.13 U4.16 U5.16 U6.10 U6.13 U6.16 U7.5 U8.10 U8.13 U8.16 U9.10 U9.13 U9.16 U10.4 U11.4 U13.B4 U13.D1 U13.E4 U14.B4 U14.D1 U14.E4 U15.14 U16.5 U17.5 U18.5 U20.5 U21.5 U26.1.5 U26.2.5 U28.8 | length 14324.7
  Top Layer w6: U14.D1@2281.26,740.63 2283.26,740.63 2292.63,750 v1(2295,750) ; v1(2390,685) 2392.3,687.3 2392.3,692.19 2399.37,699.26 U14.E4@2399.37,701.26 ; v1(2390,805) 2390,808 2399.37,817.37 U14.B4@2399.37,819.37 ; U13.E4@3787.19,478.76 3787.19,476.65 3795.75,468.09 3795.75,464.57 v1(3798.04,462.27) ; R97.2@3917.81,631.12 3917.81,676.73 3930,688.91 v1(3930,690) ; v1(4290,1225) 4290.08,1225.08 4290.08,1248.98 U9.13@4290.16,1249.06 ; v1(5925,915) 5925.3,915.3 5925.3,940.41 U2.5@5925.59,940.71 ; U3.10@6059.06,1125.79 6090.79,1125.79 6099,1134 6099,1176 6090.16,1184.84 U3.13@6059.06,1184.84 ; U3.16@6059.06,1243.9 6091.1,1243.9 6099,1236 6099,1180 ; v1(6830,980) 6830,1030.31 C24.2@6860,1060.31
  Top Layer w8: R164.2.2@1125,327.52 R164.2.2@1123.62,328.9 L7.2.2@1123.62,368.9 1123.62,375.38 1132.09,366.91 1163.09,366.91 v1(1165,365) ; R190.2.2@1186.38,568.9 1190.32,568.9 1198.13,561.09 1198.13,560.46 1229.68,528.9 R168.2.2@1233.62,528.9 1234.2,528.32 1256.68,528.32 v1(1275,510) ; L8.2.2@1320,735.28 1320,660 1334.17,645.83 1334.17,609.45 1364.45,609.45 v1(1365,610) ; v1(1770,1285) R127.2@1770,1306.38 ; C38.2@1829.69,180 v1(1850,180) ; R139.2@1960,1247.72 v1(1960,1270) ; D22.2@1990,1018.35 2009.81,1038.16 2009.81,1137.48 2000,1147.29 v1(2000,1185) 2028.62,1185 R121.2@2030,1186.38 ; v1(2840,65) 2843.39,61.61 U28.8@2887.8,61.61 ; U13.B4@3789.37,599.37 3789.69,599.69 3789.69,614.68 v1(3790,615) ; v1@5801.91,1307.78 C5.2@5819.69,1290 ; C5.2@5820,1290 5820,1250 5826.1,1243.9 U5.16@5859.06,1243.9 ; U7.5@5825.59,1330.71 5845.4,1330.71 C9.2@5870,1355.31 5878.09,1363.4 5878.09,1368.09 v1(5880,1370) ; v1(6060,1300) 6060,1280.31 C6.2@6060.31,1280 U3.16@6060.31,1245.8 ; R21.2@6150,76.38 6173.62,76.38 v1(6175,75) ; U6.10@6259.06,1125.79 6214.69,1125.79 6208,1132.47 6208,1178 6215,1185 U6.13@6260,1185 ; U6.13@6260,1184.84 6299.84,1184.84 6305,1190 6305,1235 6296.1,1243.9 U6.16@6259.06,1243.9 6260,1244.84 v1(6260,1258.79) ; R7.2@6423.62,70 v1(6423.62,95) R8.2@6423.62,120 ; R19.2@7130,72.44 R19.2@7130,76.38 7131.38,75 v1(7160,75) ; R3.2@7399.69,70 R3.2@7403.62,70 ; R4.2@7405,120 7405,71.38 R3.2@7403.62,70 ; v1(7435,70) R3.2@7403.62,70
  Top Layer w10: L7.1.2@1123.62,1550 R164.1.2@1123.62,1510 1127.56,1510 1166.03,1471.53 1188.47,1471.53 v1(1190,1470) ; R190.1.2@1186.38,1750 1190.32,1750 1222.87,1717.44 1222.87,1716.81 1229.68,1710 R168.1.2@1233.62,1710 1237.56,1710 1277.56,1670 v1(1340,1670) 1340,1715 1333.62,1721.38 R171.1.2@1333.62,1790 1333.62,1821.38 1320,1835 L8.1.2@1320,1916.38 ; R41.1@1233.62,1020 v1(1260,1020) ; J3.5@1656.5,995 v1(1720,995) ; R117.2@2380,1507.72 v1(2380,1525) ; U20.5@3337.4,805.87 3337.4,834.46 3343.26,840.31 C37.2@3390,840.31 3390.32,840 v1(3410,840) ; v1(3650,525) 3665.87,525 3670.24,520.63 U13.D1@3671.26,520.63 ; R25.2@4170,76.38 4170,80.32 4203.15,113.47 4218.47,113.47 v1(4220,115) ; v1(4180,2205) R26.2@4180,2236.38 ; C3.2@4190,1250 4230.2,1250 U9.16@4231.1,1249.06 ; U9.10@4349.21,1249.06 4349.61,1248.66 4349.61,1225.39 v1(4350,1225) ; R15.2@4453.62,70 4455,71.38 v1(4455,95) ; v1@4453.62,96.38 4455,97.76 4455,118.62 R16.2@4453.62,120 ; R17.2@4453.62,2240 v1(4490,2240) ; R17.2@4453.62,2243.62 R18.2@4453.62,2290 ; v1(4805,975) R33.1@4827.28,975 ; U11.4@4859.53,1254.17 4859.53,1279.53 v1(4860,1280) 4859.19,1280.81 4859.19,1320.84 4876.06,1337.72 R34.2@4880,1337.72 ; R34.2@4886.22,1340 4889.84,1343.62 R29.2@4920,1343.62 ; v1(5160,2210) R24.2@5160,2236.38 ; R23.2@5170,76.38 5171.38,75 v1(5200,75) ; R12.2@5433.62,120 R11.2@5433.62,70 v1(5465,70) ; R13.2@5445,2240 5443.62,2241.38 R14.2@5443.62,2290 v1(5470,2290) ; C4.2@5619.69,1290 C4.2@5619.84,1289.85 ; v1(5620,1315) 5619.84,1314.84 C4.2@5619.84,1289.85 ; U8.10@5659.06,1125.79 5618.76,1125.79 5607,1137.54 5607,1167 5625,1185 ; U8.13@5659.06,1184.84 5658.98,1184.92 5625.08,1184.92 5625,1185 ; C4.2@5619.84,1289.85 5645.15,1289.85 5659.06,1275.94 U8.16@5659.06,1243.9 5618.44,1243.9 5607,1232.46 5607,1203 5625,1185
  Top Layer w12: R22.2@6150,2236.38 6171.38,2236.38 v1(6175,2240) ; R9.2@6423.62,2240 v1(6423.62,2265) R10.2@6423.62,2290 ; R20.2@7130,2236.38 7153.62,2236.38 7155,2235 v1(7160,2235) ; R5.2@7403.62,2240 v1(7403.62,2265) R6.2@7403.62,2290
  Layer 2 w8: v1(5800,2290) 5793,2283 5793,1675.87 5817,1651.87 5817,1372 ; v1(5925,915) 5855,985 5845,985 5825,1005 5825,1105 5822.66,1107.34 5800,1130 v1(5800,1315) 5800,1355 5817,1372 ; v1(6060,1300) 6060,1325 ; v1(6260,1258.79) 6193.79,1325 6060,1325 ; 5817,1372 5819,1370 v1(5880,1370) 6015,1370 6060,1325
  Layer 2 w10: v1(4180,2205) 4180,1280 v1(4210,1250) 4235,1225 v1(4290,1225) v1(4350,1225) ; v1(4805,975) 4805,1043.47 4832.5,1070.97 4832.5,1252.5 v1(4860,1280) v1(4860,2235) ; v1(5620,1315) 5620,1778.58 5635,1793.58 v1(5635,2300)
  Layer 2 w12: v1(6775,2210) v1(6775,1320) 6800,1295 6800,1083.31 6809,1074.31 6809,1001 v1(6830,980) ; v1(7390,1270) v1(7650,1530)
  PWR w10: 2435,900 v1(2435,925)
  PWR w12: 2305,900 v1(2305,950)
  Bottom Layer w6: v1(960,1670) 960,1683.62 R189.1.2@966.38,1690 ; v1(2390,685) 2390,676.38 C29.1@2396.38,670 ; v1(2390,805) 2392.3,807.3 2392.3,812.61 2404.68,825 C32.1@2408.62,825 ; R63.2@2545,710 2545,714.5 2549.5,719 2554,719 2580,745 R69.2@2603.98,745 ; R64.2@2545,845 2545,840.5 2549.5,836 2554,836 2570,820 R67.2@2603.98,820 ; R66.2@2603.98,845 R67.2@2603.98,820 ; v1(2605,600) 2603.98,601.02 R71.2@2603.98,620 R70.2@2603.98,670 R65.2@2603.98,695 R72.2@2603.98,720 R69.2@2603.98,745 ; R43.2@3615.5,505 3620.5,510 R43.2@3625,510 3629.5,514.5 3634,514.5 3642.2,522.7 3647.7,522.7 v1(3650,525) 3651.25,523.75 3676.56,523.75 C27.1@3677.81,522.5 ; R96.2@3765,700 R42.2@3805,700 v1(3825,700) ; C30.2@3910,685 3910,674.33 3913.51,670.82 3913.59,670.82 3922.4,662.01 U18.5@3922.4,654.13 ; C30.2@3915,690 v1(3930,690) ; U10.4@6829.53,1055.83 6829.53,1022.33 6827.16,1019.96 6827.16,1014.87 R28.2@6822.28,1010 6822.28,989.19 6830,981.47 v1(6830,980) ; U4.10@7250.79,1219.06 7250.79,1189.39 7272.1,1168.07 7298.07,1168.07 7310,1180 U4.13@7310,1219.06 ; U4.13@7309.84,1219.06 7310.03,1219.24 7310.03,1245.03 7315,1250 7344.68,1250 7364.68,1270 7365,1270 7368.9,1266.1 U4.16@7368.9,1219.06 ; C10.2@7365,1270.31 7365.31,1270 v1(7390,1270) ; R69.2@2603.98,745 R68.2@2603.98,795 R67.2@2603.98,820
  Bottom Layer w8: R166.2.2@960,462.52 960.58,463.1 v1(960.58,485.58) 964.77,489.77 964.77,507.29 R189.2.2@966.38,508.9 ; v1(1095,790) 1095.55,789.45 1115.83,789.45 R172.2.2@1116.38,788.9 ; U26.2.5@1124.13,291.5 1125.28,290.35 1168.85,290.35 C142.2.2@1170,289.21 1170.39,289.61 1194.61,289.61 v1(1195,290) ; U21.5@1825.59,174.29 1825.59,176.13 1829.46,180 v1(1850,180) 1851.91,178.09 1859.47,178.09 1880,157.56 R100.2@1880,153.62 ; L1.2@1913.62,450 1920,443.62 v1(1920,390) ; v1(2000,150) 2001.91,151.91 2011.6,151.91 C36.2@2039.69,180 2053.16,193.47 2068.1,193.47 2072.79,198.16 2072.79,220.54 2074.29,222.04 U16.5@2074.29,224.41 ; v1(2100,148) 2098.09,146.09 2092.83,146.09 2085.84,139.09 2085.84,136.16 C34.2@2080,130.31 2116.34,130.31 2140.94,105.71 U15.14@2140.94,90.94 ; R95.2@2210,736.38 C28.1@2260,736.38 ; v1(2840,65) 2842.71,65 2847.7,60 C143.2@2930.31,60 2961.87,91.56 2961.87,92.19 2969.68,100 R146.1@2973.62,100 R145.1@2973.62,140 ; R110.2@2997.72,670 2997.72,666.06 3014.63,649.15 3014.63,642.81 3022.44,635 L3.2@3026.38,635 L3.2@3030,635 ; R49.2@3576.02,440 R44.2@3576.02,465 R47.2@3576.02,490 3576.02,502.5 ; R45.2@3576.02,540 R51.2@3576.02,515 3576.02,502.5 ; R46.2@3576.02,640 R50.2@3576.02,665 R48.2@3576.02,690 v1(3605,690) ; R43.2@3615.5,505 3613,502.5 3576.02,502.5 ; C8.2@5919.69,965 5919.69,923.02 5925,917.71 v1(5925,915) ; C7.2@6260,1234.69 v1(6260,1258.79) ; v1(6775,1320) R27.1@6797.28,1320
  Bottom Layer w10: R167.2.2@960,755.28 964.72,760 v1(985,760) ; R166.1.2@960,1643.62 v1(960,1670) ; v1(960,1905) R167.1.2@960,1936.38 ; v1(1085,1970) R172.1.2@1116.38,1970 ; U26.1.5@1124.13,1472.6 1125.28,1471.46 1168.85,1471.46 C142.1.2@1170,1470.31 1170.15,1470.16 1189.84,1470.16 v1(1190,1470) ; R150.2@1566.38,900 R148.2@1566.38,950 1566.38,995 ; R147.2@1566.38,1150 R149.2@1566.38,1040 1566.38,995 ; v1(1720,995) 1566.38,995 ; R89.2@2373.62,75 R90.2@2373.62,125 R91.2@2373.62,175 R92.2@2373.62,225 v1(2410,225) ; R94.2@2433.62,900 2433.62,923.62 v1(2435,925) ; v1(3790,615) 3790,612.84 3803.62,599.21 C25.1@3803.62,560 C25.1@3799.68,560 ; R113.1@3796.38,405 C26.1@3796.38,440 ; C26.1@3798.04,443.04 v1(3798.04,462.27) ; C23.2@4860,1249.69 v1(4860,1280)
  Bottom Layer w12: C28.1@2260,736.38 2261.38,735 2280,735 v1(2295,750) ; v1(2305,950) C33.2@2279.69,950 2279.69,849.17 2306.26,822.6 U17.5@2314.13,822.6
  other v1: 2975,865 3000,865 1940,1270 2355,1500 2405,1500 2355,1525 2405,1525
3V3_PG: R121.1 U23.5 U24.4 | length 348.3
  Top Layer w8: U24.4@1859.68,1339.13 1955.87,1339.13 1995,1300 1995,1245 2006.38,1233.62 R121.1@2030,1233.62 2030,1237.56 2042.44,1250 2095.79,1250 2100.47,1245.31 U23.5@2100.47,1224.72
24V: C21.2 C22.2 C116.1 C148.2 C163.2 D20.2 Q10.5 Q10.6 Q10.7 Q10.8 Q10.9@3055,1320.39 R137.2 U10.14 U10.15 U10.16 U10.17 U10.34 U10.35 U10.36 U10.37 U11.14 U11.15 U11.16 U11.17 U11.34 U11.35 U11.36 U11.37 | length 372.8
  Top Layer w8: D20.2@2778.35,1700 2778.35,1401.65 2780,1400
  Top Layer w10: v1@5008.47,1183.47 v1(5010,1185)
  Bottom Layer w8: U10.35@6907.28,1179.84 U10.35@6914.17,1179.84
  Bottom Layer w10: v1(4665,1180) 4666.53,1178.47 4666.53,1169.33 4670.86,1165 4686.26,1165 4698.98,1152.28 C148.2@4698.98,1140
  other v1: 4645,1160 4665,1160 5010,1165 5030,1165 6610,1175 6630,1175 6970,1175 6995,1175 4645,1180 5030,1185 6610,1195 6630,1195 6970,1200 6995,1200 2480,1210 2500,1210 2725,1225 2480,1230 2500,1230 2930,1245 2725,1250 2930,1270 2725,1275 2930,1295 2725,1300 2930,1320 2725,1325 2930,1345 2725,1350 2930,1370 2930,1395
25MHz.1: C127.1.1 R119.2 U19.1.9 | length 2304
  Top Layer w6.45: C127.1.1@1060,1860 C127.1.1@1060,1863.62 v1(1060,1905) 1060,1970 1090,2000 1360,2000 1380,1980 1380,1550 1315,1485 1315,870 1430,755 1430,502.44 1612.44,320 R119.2@1616.38,320
  Bottom Layer w6.45: v1(1060,1905) 1060,1902.48 1081.1,1881.38 U19.1.9@1081.1,1874.49
25MHz.2: C127.2.1 R118.2 U19.2.9 | length 1166.2
  Top Layer w6.45: C127.2.1@1060,682.52 v1(1060,725) 1060,810 1125,875 1275,875 1400,750 1400,455 1416.03,438.97 ; 1417.5,437.5 1570,285 R118.2@1616.38,285
  Bottom Layer w6.45: v1(1060,725) 1060,721.38 1081.1,700.28 U19.2.9@1081.1,693.39
+3V3_XDS110: C145.2 C146.1 C149.2 C150.2 C151.2 C152.2 C153.2 C154.1 C155.1 C156.2 D30.2 R194.2 R197.2 R198.2 R199.2 R200.2 R208.1 R211.2 U29.1 U30.7 U30.8 U30.9 U30.16 U30.26 U30.28 U30.39 U30.47 U30.51 U30.52 U30.69 U30.79 U30.90 U30.101 U30.113 U30.122 | length 1307.5
  Top Layer w6: v1(1670,1780) 1689.69,1780 C153.2@1690,1780.31 ; R197.2@1768.62,2035 R198.2@1768.62,1995 R199.2@1768.62,1955 R200.2@1768.62,1915 v1(1795,1915) ; v1(1920,1555) D30.2@1920,1583.35 ; v1(2045,1560) 2045,1575.32 C151.2@2049.69,1580 ; v1@2065,2065 2065,2045 2068.62,2048.62 C154.1@2095,2048.62 ; C156.2@2149.69,1825 v1(2170,1825) ; C156.2@2153.62,1825 C155.1@2153.62,1855 ; v1(2595,1960) 2581.38,1960 C146.1@2575,1953.62 R194.2@2615,1953.62
  Top Layer w8: v1@1750,1555 C152.2@1750,1585.31
  Bottom Layer w6: U30.47@1611.85,1791.38 1658.62,1791.38 v1(1670,1780) ; U30.51@1611.85,1854.37 1579.86,1854.37 1575.59,1858.63 1575.59,1864.46 1575,1865.05 v1(1575,1870) 1575.12,1870.12 U30.52@1611.85,1870.12 ; R211.2@1715,2196.38 1715,2200.32 1734.68,2220 1737.68,2220 v1(1738.82,2221.14) ; R211.2@1720,2195 1720,2187.44 1733.9,2173.54 U30.69@1733.9,2118.15 ; v1@1740.32,2220 1760,2239.68 R208.1@1760,2243.62 ; v1(1880,2190) 1880.31,2189.69 C150.2@1880.31,2170 1891.38,2158.94 U30.79@1891.38,2118.15 ; v1(1920,1555) 1922.87,1552.13 U30.16@1922.87,1511.85 ; v1(2045,1560) 2045,1556.75 2048.86,1552.89 U30.8@2048.86,1511.85 ; U30.90@2064.61,2118.15 2064.8,2117.95 2064.8,2070.2 v1(2065,2070) ; v1(2170,1825) 2187.87,1807.13 U30.113@2218.15,1807.13 ; v1(2170,1995) 2171.1,1996.1 U30.101@2218.15,1996.1 ; v1(2180,1665) 2180.39,1665.39 U30.122@2218.15,1665.39 ; U29.1@2583.39,1937.87 U29.1@2584.87,1937.87 ; v1(2595,1960) 2587.78,1952.78 2587.78,1940.78 U29.1@2584.87,1937.87 ; C145.2@2625,1949.69 2613.19,1937.87 U29.1@2584.87,1937.87
  Bottom Layer w8: U30.39@1611.85,1665.39 1650.39,1665.39 v1(1660,1675) ; U30.28@1733.9,1511.85 1733.96,1511.91 1733.96,1543.96 v1(1750,1560) 1765.33,1544.67 1765.33,1511.91 U30.26@1765.39,1511.85
+5V0_USB: C144.1 D31.2 J7.1 R201.1 U29.4 U29.6 | length 752.6
  Top Layer w6: R201.1@2160,2238.62 2160,2234.68 2179.68,2215 2485,2215 2511.18,2188.82 J7.1@2511.18,2125 2511.18,2053.82 2528.31,2036.69 D31.2@2528.31,2000 2515,1986.69 C144.1@2515,1953.62 2513.62,1955 v1(2490,1955)
  Bottom Layer w6: v1(2490,1955) v1@2490,1951.54 ; U29.4@2506.61,1886.69 2493.51,1886.69 2490,1890.21 v1@2490,1951.54 ; U29.6@2506.61,1937.87 2503.66,1937.87 v1@2490,1951.54
\Fault: U1.1.20 U1.2.20 U1.3.20 U1.4.20 U1.5.20 U1.6.20 U1.7.20 U1.8.20 U12.G1 | length 7060.6
  Top Layer w4: U12.G1@3293.11,410.43 3308.92,410.43 3325.49,427 3353.79,427 3360.79,420 3389.16,420 3406.16,403 3408.31,403 3494,317.31 3494,233.95 3583.95,144 3876.63,144 3982.63,250 v1(4098.99,250) ; v1(4140,1055) 4271.21,1055 4276.21,1060 v1(4280,1060) 4280,1073.69 4306.31,1100 v1(4405,1100) 4430,1100 4595,935 5120,935 5255,1070 ; v1@5255,1078.79 v1(5255,1085) 5255,1070 ; v1(6270,1050) 6249,1029 6064,1029 5928,893 5799.5,893 5727.5,965 5543.69,965 5448.69,1060 5345,1060 5330,1045 5275,1045 5255,1065 5255,1070 ; v1(6360,1110) 6361.66,1108.34 6361.66,1098.44 6427.1,1033 6734.53,1033 6742.53,1025 6760,1025 6830,955 6915,955 v1(6920,960)
  Layer 2 w4: v1(5255,1085) 5256.61,1086.61 5256.61,1171.61 5275,1190 v1(5350,1190) ; v1(6270,1050) 6300,1050 v1(6360,1110) ; v1(6920,960) 6920,1095 6979,1154 7174,1154 7223.94,1203.94 7315,1203.94 ; v1(7245,1045) 7315,1115 7315,1203.94 ; v1(7335,1270) 7335,1233.11 7315,1213.11 7315,1203.94
  Bottom Layer w4: v1(4098.99,250) 4061,287.99 4061,829.18 4087,855.18 4087,981.75 4117,1011.75 4117,1032 v1(4140,1055) ; v1(4280,1060) 4297.72,1042.28 U1.8.20@4297.72,1015.3 ; U1.7.20@4363.7,1346.91 4363.7,1327.51 4390,1301.21 4390,1115 v1(4405,1100) ; v1(5255,1085) 5255,1065 5281.97,1038.03 U1.6.20@5281.97,1015.3 ; U1.5.20@5347.95,1346.91 5348.98,1345.89 5348.98,1191.02 v1(5350,1190) ; U1.3.20@6266.22,1015.3 6266.22,1033 6268.22,1035 6268.22,1048.22 v1(6270,1050) ; U1.4.20@6332.2,1346.91 6332.2,1340.22 6360,1312.42 v1(6360,1110) ; v1(7245,1045) 7245,1041.21 7250.47,1035.74 U1.1.20@7250.47,1015.3 ; U1.2.20@7316.46,1346.91 7316.46,1288.54 v1(7335,1270)
\FLT: R29.1 U10.2 U11.2 U12.G2 | length 5822.9
  Top Layer w4: U12.G2@3267.52,410.43 3279.91,422.82 3310,422.82 3322.18,435 3357.1,435 3360.1,432 3388.47,432 3409.47,411 3411.63,411 3502,320.63 3502,237.27 3587.27,152 3873.31,152 3988.31,267 4108,267 4133,242 4887,242 v1(4920,275) 4921.21,275 4931.21,285 5040.25,285 5075.26,250 6034.49,250 6060.49,224 6859,224 v1(6870,235) ; U11.2@4898.9,1254.17 4899.45,1254.72 v1@4899.45,1280 ; v1(4900,1280) 4902.63,1282.63 4910.19,1282.63 4920,1292.44 R29.1@4920,1296.38
  Bottom Layer w4: v1(4900,1280) 4920.01,1259.99 4945,1235 4945,1082.03 4974,1053.03 4974,329 v1(4920,275) ; U10.2@6868.9,1055.83 6868.9,1036.1 6875,1030 6875,243.79 6870,238.79 v1(6870,235)
\POR: R93.1 U12.V3 U20.4 | length 1863.7
  Top Layer w3.5: 3254.72,754.72 3255,755
  Top Layer w4: R93.1@2053.62,300 v1(2085,300) ; 3254.72,711.38 3254.72,754.72 ; 3255,755 3262.6,762.6
  Top Layer w5: U12.V3@3241.93,689.55 U12.V3@3241.93,691.93 3254.72,704.72 3254.72,711.38 ; 3262.6,762.6 U20.4@3262.6,805.87 3283.08,805.87 3289.44,812.23 3289.44,824.44 v1(3290,825)
  Bottom Layer w8: v1(2085,300) 2368.03,300 2639.01,570.99 2684.01,570.99 2708,594.97 2708,734.97 2872.03,899 3216,899 3220,895 3245,895 3255,905 3315.63,905 3320.31,900.31 3320.31,900 3325,895.31 3325,885 3290,850 v1(3290,825)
